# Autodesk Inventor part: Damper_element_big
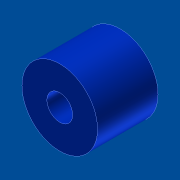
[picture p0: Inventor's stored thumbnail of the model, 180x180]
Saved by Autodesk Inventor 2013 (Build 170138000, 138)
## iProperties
Shininess: 20.0
Length Units: 11269
Angle Units: 11279
Time Units: 11290
Mass Units: 11283
Length Display Precision: 3
Angle Display Precision: 2
Created: 2001-04
Part Number: Damper_element_big
Material: Standard
Document SubType Name: Modellieren
Designer: dl
Density: 1 g/cm^3
Density: 0.0
Volumn: 0.0
Area: 0.0
PropertySet Name: Model Information
Control State: 0
Master: False
Checked Out: False
Author: dl
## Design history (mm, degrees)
body "Solid1"
sketch "Sketch1"
  geometry: C1 r 12.5 at (0, 0); C2 r 4.25 at (0, 0)
  constraints: 2 centre point, 1 coincident
  dimensions: "d0" = 25 diameter of C1; "d1" = 8.5 diameter of C2
extrude "Extrusion1" new body sketch "Sketch1" distance "d2" = 20; taper "d3" = 0 deg
